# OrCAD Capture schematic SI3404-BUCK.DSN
size B; title: Si3404-Buck; rev: 2.1; note: SI3404-BUCK
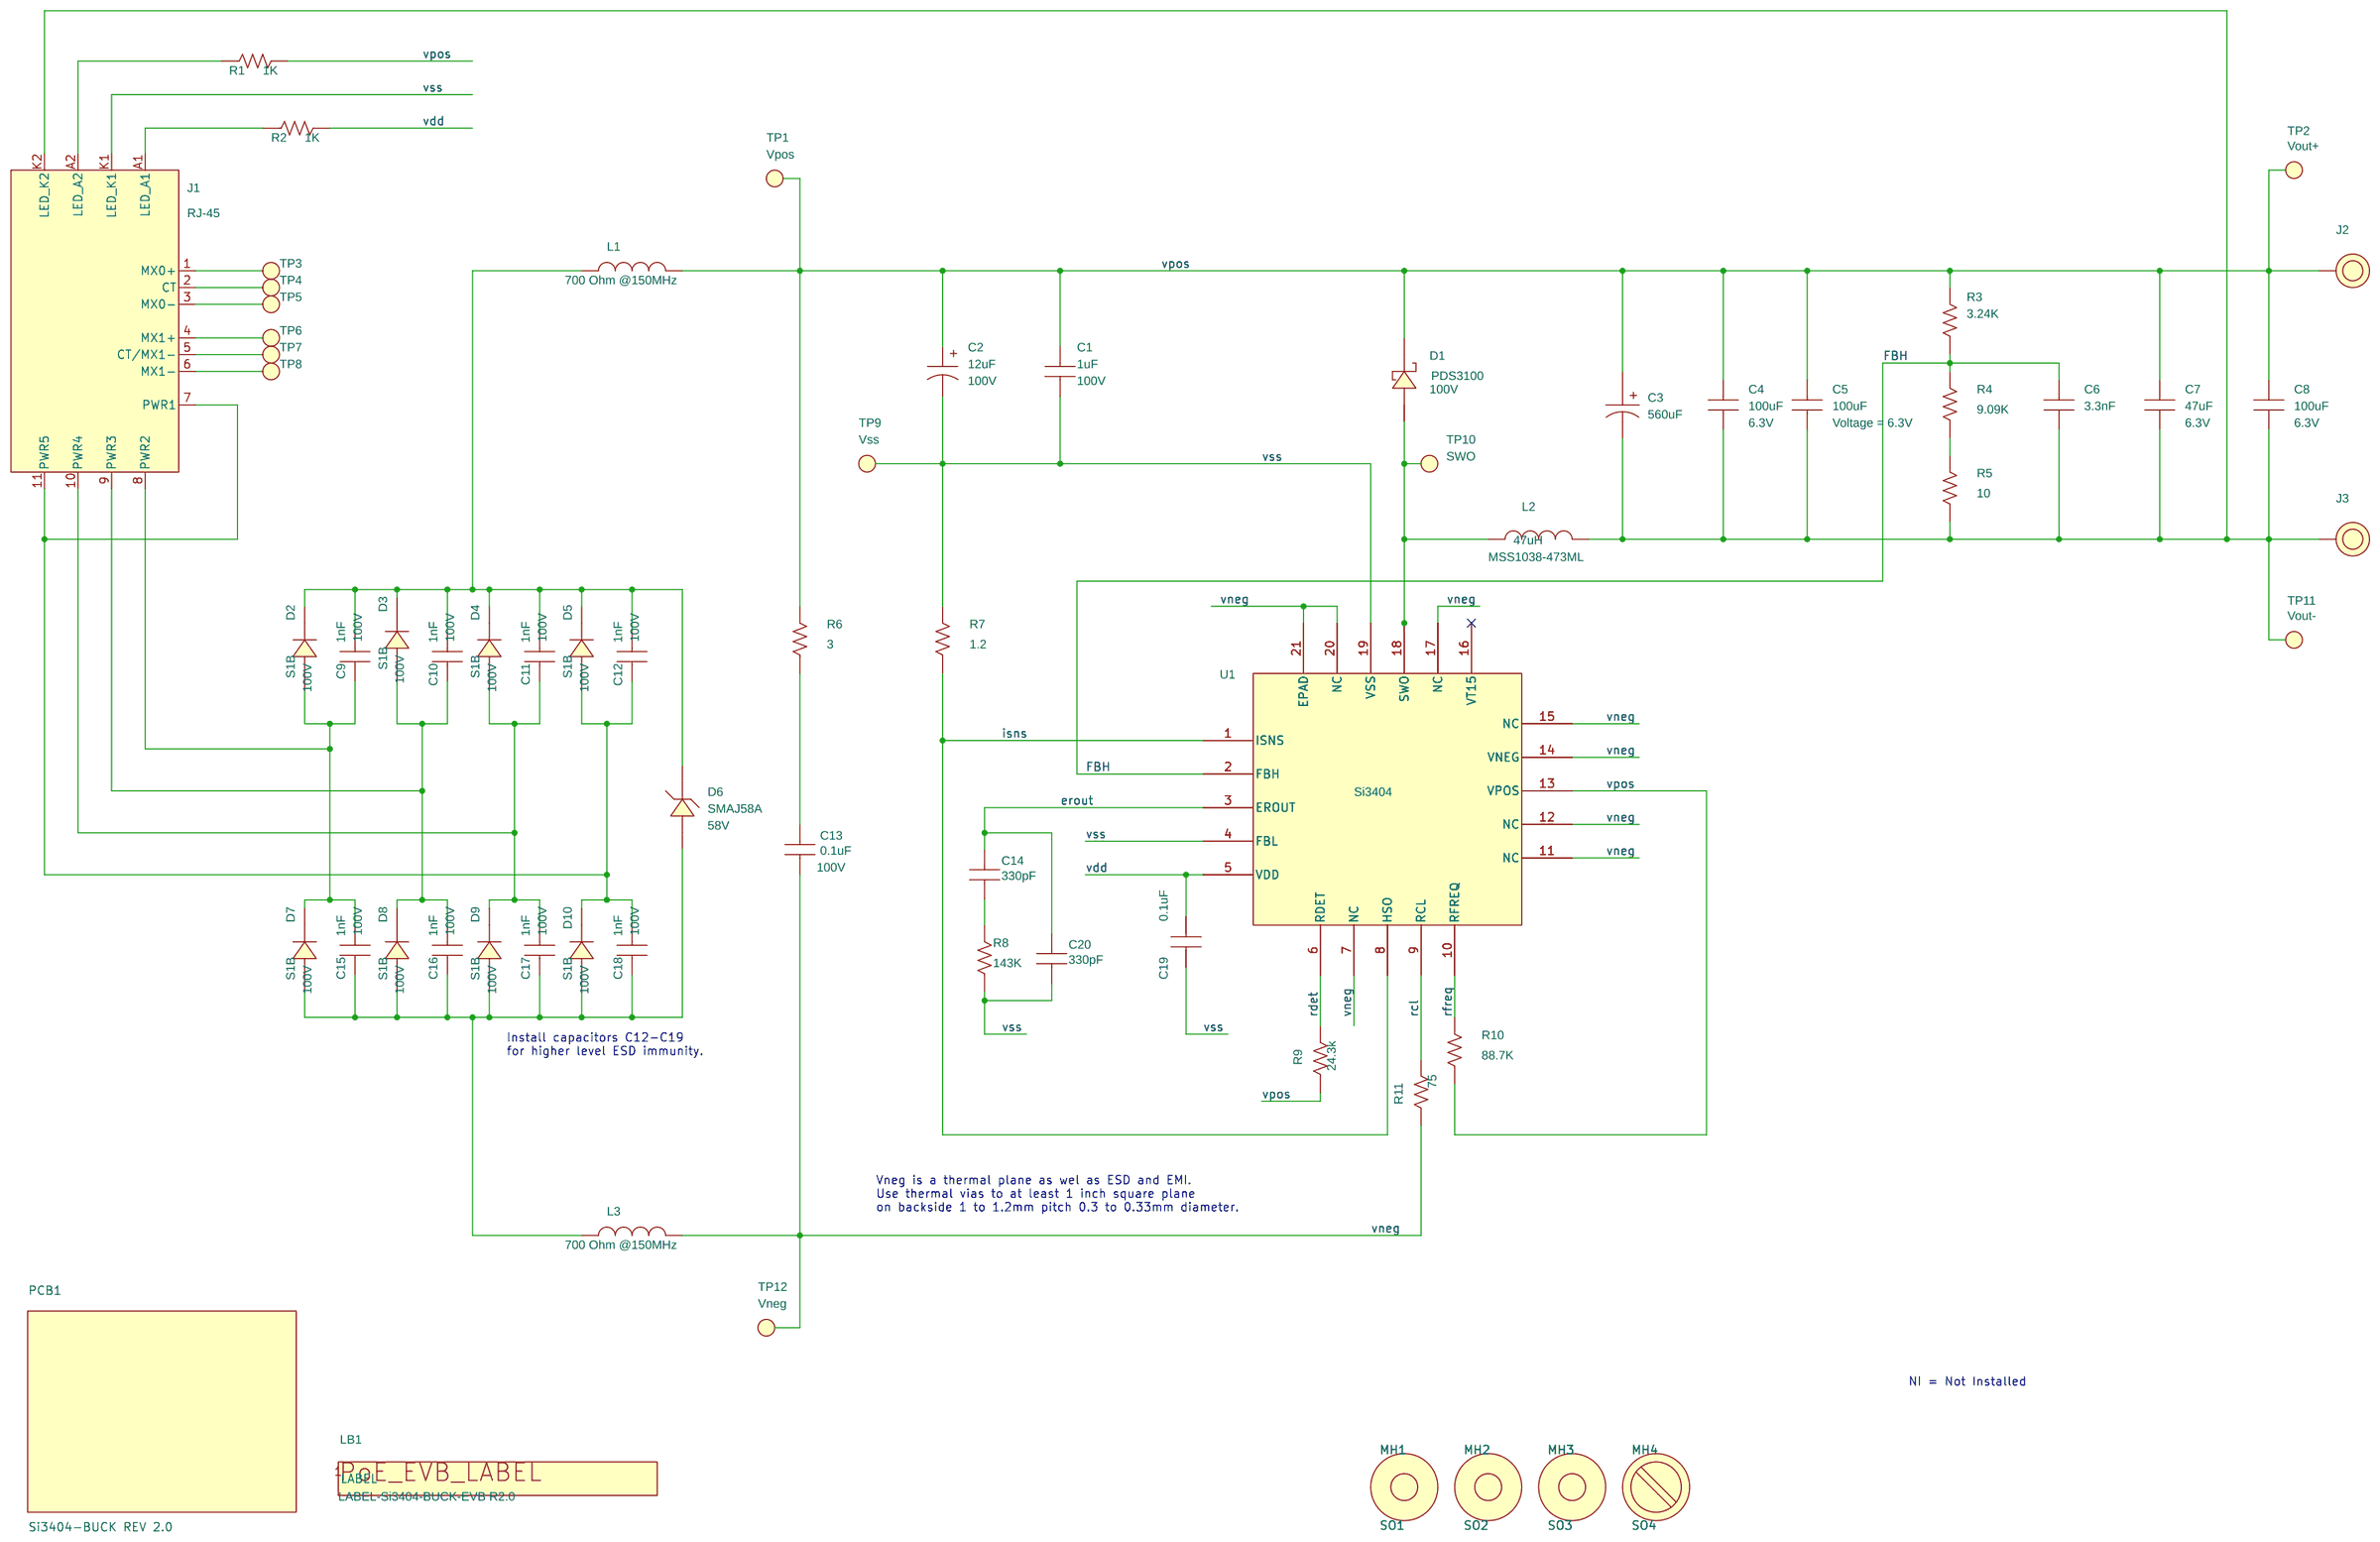
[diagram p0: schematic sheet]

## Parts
C1  1uF  [C1210]
C2  12uF  [C2.5X6.3MM-RAD]
C3  560uF  [C3.5X8MM-RAD]
C4  100uF  [C1210]
C5  100uF  [C1210]
C6  3.3nF  [C0805]
C7  47uF  [C0805]
C8  100uF  [C1210]
C9  1nF  [C0603]
C10  1nF  [C0603]
C11  1nF  [C0603]
C12  1nF  [C0603]
C13  0.1uF  [C0805]
C14  330pF  [C0805]
C15  1nF  [C0603]
C16  1nF  [C0603]
C17  1nF  [C0603]
C18  1nF  [C0603]
C19  0.1uF  [C0805]
C20  330pF  [C0805]
D1  PDS3100  [POWERDI-5]
D2  S1B  [DO-214AC]
D3  S1B  [DO-214AC]
D4  S1B  [DO-214AC]
D5  S1B  [DO-214AC]
D6  SMAJ58A  [DO-214AC]
D7  S1B  [DO-214AC]
D8  S1B  [DO-214AC]
D9  S1B  [DO-214AC]
D10  S1B  [DO-214AC]
J1  RJ-45  [RJ45-SI-52004]
J2  BND_POST  [BANANA-JACK]
J3  BND_POST  [BANANA-JACK]
L1  742792040  [L0805]
L2  47uH  [IND-MSS1038]
L3  742792040  [L0805]
LB1  LABEL-Si3404-BUCK-EVB R2.0  [PTL-14-477]
MH1  4-40  [MH-125NP]
MH2  4-40  [MH-125NP]
MH3  4-40  [MH-125NP]
MH4  4-40  [MH-125NP]
PCB1  Si3404-BUCK REV 2.0  [N/A]
R1  1K  [R0805]
R2  1K  [R0805]
R3  3.24K  [R0805]
R4  9.09K  [R0805]
R5  10  [R0805]
R6  3  [R0805]
R7  1.2  [R0805]
R8  143K  [R0805]
R9  24.3k  [R0805]
R10  88.7K  [R0805]
R11  75  [R0805]
SO1  STANDOFF
SO2  STANDOFF
SO3  STANDOFF
SO4  STANDOFF
TP1  BLACK  [TESTPOINT]
TP2  BLACK  [TESTPOINT]
TP3  BLACK  [TESTPOINT]
TP4  BLACK  [TESTPOINT]
TP5  BLACK  [TESTPOINT]
TP6  BLACK  [TESTPOINT]
TP7  BLACK  [TESTPOINT]
TP8  BLACK  [TESTPOINT]
TP9  BLACK  [TESTPOINT]
TP10  BLACK  [TESTPOINT]
TP11  BLACK  [TESTPOINT]
TP12  BLACK  [TESTPOINT]
U1  Si3404  [QFN20M4X4P0.5]

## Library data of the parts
C1 = CAP_NP: CAP, 1uF, 100V, ±10%, X7R, 1210; Manufacturer: Venkel; ManufacturerPN: C1210X7R101-105K; SiLabsPN: C1210X7R101-105K; Tolerance: ±10%; Type: X7R; Voltage: 100V; Datasheet: PID_C.pdf
C2 = CAP_POL_ALT: CAP, 12uF, 100V, ±20%, AL, 6.3X11.2MM; Manufacturer: Panasonic; ManufacturerPN: EEUFC2A120; SiLabsPN: EEUFC2A120; Tolerance: ±20%; Type: Alum_Elec; Voltage: 100V; Datasheet: ABA0000CE22.pdf
C3 = CAP_POL: CAP, 560uF, 6.3V, ±20%, AL, 8.0X11.5MM; Manufacturer: Panasonic; ManufacturerPN: EEUFM0J561; Part_Type: CAP/POL; SiLabsPN: EEUFM0J561; Tolerance: ±20%; Type: Alum_Elec; Voltage: 6.3V; Datasheet: ABA0000CE108.pdf
C4 C5 C8 = CAP_NP: CAP, 100uF, 6.3V, ±10%, X5R, 1210; Manufacturer: Venkel; ManufacturerPN: C1210X5R6R3-107K; SiLabsPN: C1210X5R6R3-107K; Tolerance: ±10%; Type: X5R; Voltage: 6.3V; Datasheet: PID_C.pdf
C6 = CAP_NP: CAP, 3.3nF, 16V, ±10%, X7R, 0805; Manufacturer: Venkel; ManufacturerPN: C0805X7R160-332K; SiLabsPN: C0805X7R160-332K; Tolerance: ±10%; Type: X7R; Voltage: 16V; Datasheet: PID_C.pdf
C7 = CAP_NP: CAP, 47uF, 6.3V, ±20%, X5R, 0805; Manufacturer: Venkel; ManufacturerPN: C0805X5R6R3-476M; SiLabsPN: C0805X5R6R3-476M; Tolerance: ±20%; Type: X5R; Voltage: 6.3V; Datasheet: PID_C.pdf
C9-C12 C15-C18 = CAP_NP: CAP, 1nF, 100V, ±10%, X7R, 0603; Manufacturer: Venkel; ManufacturerPN: C0603X7R101-102K; SiLabsPN: C0603X7R101-102K; Tolerance: ±10%; Type: X7R; Voltage: 100V; Datasheet: PID_C.pdf
C13 = CAP_NP: CAP, 0.1uF, 100V, ±10%, X7R, 0805; Manufacturer: Venkel; ManufacturerPN: C0805X7R101-104K; SiLabsPN: C0805X7R101-104K; Tolerance: ±10%; Type: X7R; Voltage: 100V; Datasheet: PID_C.pdf
C14 C20 = CAP_NP: CAP, 330pF, 50V, ±1%, C0G, 0805; Manufacturer: Venkel; ManufacturerPN: C0805C0G500-331F; SiLabsPN: C0805C0G500-331F; Tolerance: ±1%; Type: C0G; Voltage: 50V; Datasheet: PID_C.pdf
C19 = CAP_NP: CAP, 0.1uF, 16V, ±10%, X7R, 0805; Manufacturer: Venkel; ManufacturerPN: C0805X7R160-104K; SiLabsPN: C0805X7R160-104K; Tolerance: ±10%; Type: X7R; Voltage: 16V; Datasheet: PID_C.pdf
D1 = DIODE_SCHOTTKY_DUAL_ANODE_3PIN: DIO, SCHOTTKY, 100V, 3A, PowerDI-5; Manufacturer: Diodes Inc.; ManufacturerPN: PDS3100-13; Rating: 3A; SiLabsPN: PDS3100-13; Type: Schottky; Voltage: 100V; Datasheet: ds30487.pdf
D2-D5 D7-D10 = DIODE: DIO, SINGLE, 100V, 1.0A, SMA; Manufacturer: Fairchild; Rating: 1.0A; Type: Single; Voltage: 100V; Datasheet: S1A.pdf
D6 = DIODE_ZENER: DIO, TVS, UNIDIR, 58V, 400W; Manufacturer: Littelfuse; Rating: 400W; Type: GP; Voltage: 58V; Datasheet: smaj.pdf
J1 = MAGJACK_3: CONN, RJ-45, MAGJACK, 1 Port PoE; Manufacturer: Bel; ManufacturerPN: SI-52003-F; SiLabsPN: SI-52003-F; Type: Receptacle; Datasheet: SI-52003-F.pdf
J2 J3 = BINDING-POST: CONN, BANANA JACK, Threaded uninsulated; Manufacturer: ABBATRON HH SMITH; ManufacturerPN: 101; Part_Type: CON; Rating: 15A; SiLabsPN: 101; Type: BANANA; Datasheet: SD-101.pdf
L1 L3 = Ferrite_Bead: FERRITE BEAD, 700 Ohm @150MHZ, 0805; Manufacturer: Wurth; Rating: 2000mA; Type: SMT; Voltage: 700 Ohm @150MHz; Datasheet: 742792040.pdf
L2 = INDUCTOR: INDUCTOR, POWER, Shielded, 47uH, ±20%, 1.6A, SMD; Manufacturer: Coilcraft; ManufacturerPN: MSS1038-473ML; Part_Type: IND/SMT; Rating: 1.6A; SiLabsPN: MSS1038-473ML; Tolerance: ±20%; Type: Shielded; Datasheet: mss1038.pdf
LB1 = PoE_EVB_Label: LABEL, PDB, POLYIMIDE, WHITE, 1.00 in. X 0.187 in., FONT 2; Manufacturer: Skyworks; Type: POLYIMIDE, WHITE; Datasheet: Brady TLS2200 Label PTL-14-477.pdf
MH1-MH4 = SCREW-Small: HDW, SCREW, 4-40 x 1/4 in. Pan Head, Slotted, Nylon; Manufacturer: Richco Plastic Co; ManufacturerPN: NSS-4-4-01; SiLabsPN: NSS-4-4-01; Type: SCREW; Datasheet: RichcoPlasticCo_Screws.pdf
PCB1 = PCB: PCB, BARE BOARD, Si3404-BUCK REV 2.0; Manufacturer: Skyworks; Type: BARE PCB
R1 R2 = RES_V: RES, 1K, 1/10W, ±1%, ThickFilm, 0805; Manufacturer: Venkel; ManufacturerPN: CR0805-10W-1001F; Part_Type: RES/SMT; Rating: 1/10W; SiLabsPN: CR0805-10W-1001F; Tolerance: ±1%; Type: ThickFilm; Datasheet: PID_CR.pdf
R3 = RES_V: RES, 3.24K, 1/8W, ±1%, ThickFilm, 0805; Manufacturer: Vishay; ManufacturerPN: CRCW08053K24FKEA; Part_Type: RES/SMT; Rating: 1/8W; SiLabsPN: CR0805-8W-3241F; Tolerance: ±1%; Type: ThickFilm; Datasheet: dcrcwe3-109170.pdf
R4 = RES: RES, 9.09K, 1/10W, ±25PPM, ±0.5%, ThinFilm, 0805; Manufacturer: Susumu; ManufacturerPN: RR1220P-9091-D-M; Rating: 1/10W; SiLabsPN: TFCR0805-10W-E-9091D; Tolerance: ±0.5%; Type: ±25PPM; Datasheet: n_catalog_partition05_en.pdf
R5 = RES: RES, 10 Ohm, 1/10W, ±1%, ThickFilm, 0805; Manufacturer: Venkel; ManufacturerPN: CR0805-10W-10R0F; Rating: 1/10W; SiLabsPN: CR0805-10W-10R0F; Tolerance: ±1%; Type: ThickFilm; Datasheet: PID_CR.pdf
R6 = RES: RES, 3 Ohm, 1/8W, ±1%, ThickFilm, 0805; Manufacturer: Venkel; ManufacturerPN: CR0805-8W-3R00FT; Rating: 1/8W; SiLabsPN: CR0805-8W-3R00F; Tolerance: ±1%; Type: ThickFilm; Datasheet: PID_CR.pdf
R7 = RES: RES, 1.2 Ohm, 1/10W, ±5%, ThickFilm, 0805; Manufacturer: Venkel; ManufacturerPN: CR0805-10W-1R2J; Rating: 1/10W; SiLabsPN: CR0805-10W-1R2J; Tolerance: ±5%; Type: ThickFilm; Datasheet: PID_CR.pdf
R8 = RES: RES, 143K, 1/10W, ±1%, ThickFilm, 0805; Manufacturer: Venkel; ManufacturerPN: CR0805-10W-1433F; Rating: 1/10W; SiLabsPN: CR0805-10W-1433F; Tolerance: ±1%; Type: ThickFilm; Datasheet: PID_CR.pdf
R9 = RES: RES, 24.3k, 1/8W, ±1%, ThickFilm, 0805; Manufacturer: vishay; ManufacturerPN: CRCW080524K3FKEA; Rating: 1/8W; SiLabsPN: CR0805-8W-2432F; Tolerance: ±1%; Type: ThickFilm; Datasheet: dcrcwe3-109170.pdf
R10 = RES: RES, 88.7K, 1/8W, ±1%, ThickFilm, 0805; Manufacturer: Vishay; ManufacturerPN: CRCW080588K7FKEA; Rating: 1/8W; SiLabsPN: CR0805-8W-8872F; Tolerance: ±1%; Type: ThickFilm; Datasheet: dcrcwe3-109170.pdf
R11 = RES: RES, 75 Ohm, 1/10W, ±1%, ThickFilm, 0805; Manufacturer: Venkel; ManufacturerPN: CR0805-10W-75R0F; Rating: 1/10W; SiLabsPN: CR0805-10W-75R0F; Tolerance: ±1%; Type: ThickFilm; Datasheet: PID_CR.pdf
SO1-SO4 = STANDOFF: HDW, STANDOFF, 4-40 X 1/2" , Nylon; Manufacturer: SPC Technology; ManufacturerPN: 2397; SiLabsPN: 2397; Datasheet: SPC_Technology_spacers.pdf
TP1 = TEST_POINT: TESTPOINT, BLACK, 0.050" LOOP, PTH; Manufacturer: Keystone; ManufacturerPN: 5001; SiLabsPN: 5001; Silk: Vpos; Type: LOOP; Datasheet: Keystone_thm_datasheet.pdf
TP2 = TEST_POINT: TESTPOINT, BLACK, 0.050" LOOP, PTH; Manufacturer: Keystone; ManufacturerPN: 5001; SiLabsPN: 5001; Silk: Vout+; Type: LOOP; Datasheet: Keystone_thm_datasheet.pdf
TP3-TP8 = TEST_POINT: TESTPOINT, BLACK, 0.050" LOOP, PTH; Manufacturer: Keystone; ManufacturerPN: 5001; SiLabsPN: 5001; Silk: <Silk>; Type: LOOP; Datasheet: Keystone_thm_datasheet.pdf
TP9 = TEST_POINT: TESTPOINT, BLACK, 0.050" LOOP, PTH; Manufacturer: Keystone; ManufacturerPN: 5001; SiLabsPN: 5001; Silk: Vss; Type: LOOP; Datasheet: Keystone_thm_datasheet.pdf
TP10 = TEST_POINT: TESTPOINT, BLACK, 0.050" LOOP, PTH; Manufacturer: Keystone; ManufacturerPN: 5001; SiLabsPN: 5001; Silk: SWO; Type: LOOP; Datasheet: Keystone_thm_datasheet.pdf
TP11 = TEST_POINT: TESTPOINT, BLACK, 0.050" LOOP, PTH; Manufacturer: Keystone; ManufacturerPN: 5001; SiLabsPN: 5001; Silk: Vout-; Type: LOOP; Datasheet: Keystone_thm_datasheet.pdf
TP12 = TEST_POINT: TESTPOINT, BLACK, 0.050" LOOP, PTH; Manufacturer: Keystone; ManufacturerPN: 5001; SiLabsPN: 5001; Silk: Vneg; Type: LOOP; Datasheet: Keystone_thm_datasheet.pdf
U1 = Si3404: IC, FULLY-INTEGRATED 802.3-COMPLIANT PoE PD INTERFACE AND LOW-EMI SWITCHING REGULATOR, QFN20; Manufacturer: Skyworks; ManufacturerPN: Si3404-A-GM; SiLabsPN: Si3404-A-GM; Type: PD; Voltage: 120V; Datasheet: Si3404.pdf

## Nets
vdd: C19.1 R2.1 U1.5(VDD)
vss: C1.1 C2.2 C19.2 C20.2 J1.K1(LED) R7.2 R8.1 TP9.1(Point) U1.4(FBL) U1.19(VSS)
erout: C14.1 C20.1 U1.3(EROUT)
FBH: C6.1 R3.2 R4.2 U1.2(FBH)
isns: R7.1 U1.1(ISNS) U1.8(HSO)
LABEL: LB1.1(LABEL)
rcl: R11.2 U1.9(RCL)
rdet: R9.2 U1.6(RDET)
rfreq: R10.2 U1.10(RFREQ)
vneg: C13.2 L3.2 R11.1 TP12.1(Point) U1.7(NC) U1.11(NC) U1.12(NC) U1.14(VNEG) U1.15(NC) U1.17(NC) U1.20(NC) U1.21(EPAD)
vpos: C1.2 C2.1 C3.1 C4.1 C5.1 C7.2 C8.1 D1.K(CATHODE) J2.1(BP) L1.2 R1.1 R3.1 R6.2 R9.1 R10.1 TP1.1(Point) TP2.1(Point) U1.13(VPOS)
N317144: J1.A1(LED) R2.2
N1344300: J1.A2(LED) R1.2
N1417589: C9.1 C15.2 D2.A(ANODE) D7.K(CATHODE) J1.8(PWR2)
N1417594: C10.1 C16.2 D3.A(ANODE) D8.K(CATHODE) J1.9(PWR3)
N1417609: C11.1 C17.2 D4.A(ANODE) D9.K(CATHODE) J1.10(PWR4)
N1417624: C12.1 C18.2 D5.A(ANODE) D10.K(CATHODE) J1.7(PWR1) J1.11(PWR5)
N1473877: C3.2 C4.2 C5.2 C6.2 C7.1 C8.2 J1.K2(LED) J3.1(BP) L2.2 R5.1 TP11.1(Point)
N1501769: C15.1 C16.1 C17.1 C18.1 D6.A(ANODE) D7.A(ANODE) D8.A(ANODE) D9.A(ANODE) D10.A(ANODE) L3.1
N1501891: C9.2 C10.2 C11.2 C12.2 D2.K(CATHODE) D3.K(CATHODE) D4.K(CATHODE) D5.K(CATHODE) D6.K(CATHODE) L1.1
N1503918: D1.A1(ANODE) D1.A2(ANODE) L2.1 TP10.1(Point) U1.18(SWO)
N1518774: C14.2 R8.2
N1525569: J1.6(MX1-) TP8.1(Point)
N1525571: J1.4(MX1+) TP6.1(Point)
N1525573: J1.3(MX0-) TP5.1(Point)
N1525575: J1.2(CT) TP4.1(Point)
N1525577: J1.5(CT/MX1-) TP7.1(Point)
N1525579: J1.1(MX0+) TP3.1(Point)
N1548686: R4.1 R5.2
N1549456: C13.1 R6.1

Not connected (* = marked no-connect by the designer): U1 16(VT15)*

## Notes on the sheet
- Install capacitors C12-C19
  for higher level ESD immunity.
- Vneg is a thermal plane as wel as ESD and EMI.
  Use thermal vias to at least 1 inch square plane
  on backside 1 to 1.2mm pitch 0.3 to 0.33mm diameter.
- NI = Not Installed
